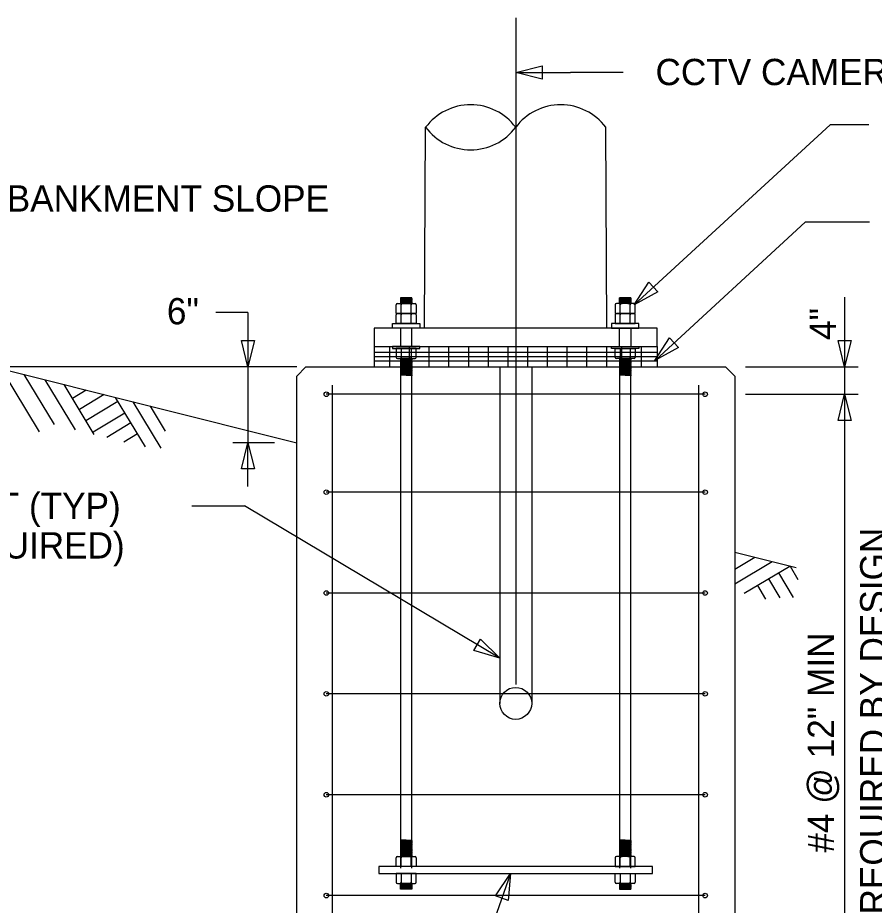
# Model space of a CAD drawing. Extents: x 1299104.6 to 1299141.4, y 239713.3 to 239735.3.
# Drawn here: x 1299109.376 to 1299113.286, y 239719.565 to 239723.616 of the extents above; entities that cross this region are included whole.
import ezdxf

# ---------------------------------------------------------------- set-up
doc = ezdxf.new("R2010")
doc.units = 0
for name, color, linetype in [('DIM TXT', 7, 'Continuous'), ('Level 3', 7, 'Continuous'), ('Level 4', 7, 'Continuous'), ('Level 7', 7, 'Continuous'), ('Level 8', 7, 'Continuous')]:
    doc.layers.add(name, color=color, linetype=linetype)

msp = doc.modelspace()

# ---------------------------------------------------------------- linework, layer by layer
at = {"layer": 'Level 3'}
for p, q in [((1299111.2328, 239722.1991), (1299111.2383, 239723.1157)), ((1299112.0662, 239722.1991), (1299112.0607, 239723.1157)), ((1299108.4734, 239722.22), (1299110.6495, 239721.676)), ((1299112.2953, 239722.1991), (1299111.0037, 239722.1991)), ((1299111.0037, 239722.1991), (1299111.0037, 239722.1157)), ((1299112.2953, 239722.1157), (1299112.2953, 239722.1991)), ((1299111.0037, 239722.1157), (1299112.2953, 239722.1157)), ((1299110.6495, 239721.9803), (1299110.6912, 239722.022)), ((1299110.6912, 239722.022), (1299112.6078, 239722.022)), ((1299111.5766, 239722.022), (1299111.5766, 239720.4861)), ((1299111.7224, 239722.022), (1299111.7224, 239720.4861)), ((1299112.6078, 239722.022), (1299112.6495, 239721.9803)), ((1299110.6495, 239719.022), (1299110.6495, 239721.9803)), ((1299112.6495, 239721.9803), (1299112.6495, 239719.022)), ((1299110.8136, 239718.147), (1299110.8136, 239721.9387)), ((1299112.4854, 239718.147), (1299112.4854, 239721.9387)), ((1299112.5141, 239721.897), (1299110.7849, 239721.897)), ((1299112.5141, 239721.4502), (1299110.7849, 239721.4502)), ((1299112.6495, 239721.176), (1299112.9298, 239721.1059)), ((1299112.5141, 239720.9898), (1299110.7849, 239720.9898)), ((1299112.5141, 239720.5294), (1299110.7849, 239720.5294)), ((1299112.5141, 239720.069), (1299110.7849, 239720.069)), ((1299112.2745, 239719.7411), (1299111.0245, 239719.7411)), ((1299111.0245, 239719.7411), (1299111.0245, 239719.7098)), ((1299112.2745, 239719.7098), (1299112.2745, 239719.7411)), ((1299111.0245, 239719.7098), (1299112.2745, 239719.7098)), ((1299112.5141, 239719.6086), (1299110.7849, 239719.6086))]:
    msp.add_line(p, q, dxfattribs=at)
for centre, radius in [((1299110.7849, 239721.897), 0.0104), ((1299112.5141, 239721.897), 0.0104), ((1299110.7849, 239721.4502), 0.0104), ((1299112.5141, 239721.4502), 0.0104), ((1299110.7849, 239720.9898), 0.0104), ((1299112.5141, 239720.9898), 0.0104), ((1299110.7849, 239720.5294), 0.0104), ((1299111.6495, 239720.4861), 0.0729), ((1299112.5141, 239720.5294), 0.0104), ((1299110.7849, 239720.069), 0.0104), ((1299112.5141, 239720.069), 0.0104), ((1299110.7849, 239719.6086), 0.0104), ((1299112.5141, 239719.6086), 0.0104)]:
    msp.add_circle(centre, radius, dxfattribs=at)
for centre, start, end in [((1299111.4439, 239722.9615), 36.8699, 143.1301), ((1299111.8551, 239722.9615), 36.8699, 143.1301), ((1299111.4439, 239723.2699), 216.8699, 323.1301)]:
    msp.add_arc(centre, 0.257, start, end, dxfattribs=at)
at = {"layer": 'Level 4'}
for p, q in [((1299111.1267, 239722.2655), (1299111.1267, 239722.311)), ((1299111.1723, 239722.2655), (1299111.1723, 239722.311)), ((1299112.1267, 239722.2655), (1299112.1267, 239722.311)), ((1299112.1723, 239722.2655), (1299112.1723, 239722.311)), ((1299111.1267, 239722.2199), (1299111.1267, 239722.2655)), ((1299111.1723, 239722.2199), (1299111.1723, 239722.2655)), ((1299112.1267, 239722.2199), (1299112.1267, 239722.2655)), ((1299112.1723, 239722.2199), (1299112.1723, 239722.2655)), ((1299111.0037, 239722.1157), (1299111.0037, 239722.022)), ((1299111.0732, 239722.1157), (1299111.0732, 239722.022)), ((1299111.1267, 239722.1053), (1299111.1267, 239722.0597)), ((1299111.1632, 239722.1157), (1299111.1632, 239722.022)), ((1299111.1723, 239722.1053), (1299111.1723, 239722.0597)), ((1299111.2532, 239722.1157), (1299111.2532, 239722.022)), ((1299111.3432, 239722.1157), (1299111.3432, 239722.022)), ((1299111.4332, 239722.1157), (1299111.4332, 239722.022)), ((1299111.5232, 239722.1157), (1299111.5232, 239722.022)), ((1299111.6132, 239722.1157), (1299111.6132, 239722.022)), ((1299111.7032, 239722.1157), (1299111.7032, 239722.022)), ((1299111.7932, 239722.1157), (1299111.7932, 239722.022)), ((1299111.8832, 239722.1157), (1299111.8832, 239722.022)), ((1299111.9732, 239722.1157), (1299111.9732, 239722.022)), ((1299112.0632, 239722.1157), (1299112.0632, 239722.022)), ((1299112.1267, 239722.1053), (1299112.1267, 239722.0597)), ((1299112.132, 239722.1157), (1299112.132, 239722.022)), ((1299112.1723, 239722.1053), (1299112.1723, 239722.0597)), ((1299112.222, 239722.1157), (1299112.222, 239722.022)), ((1299112.2953, 239722.1157), (1299112.2953, 239722.022)), ((1299111.0037, 239722.0893), (1299112.2953, 239722.0893)), ((1299111.0037, 239722.0693), (1299112.2953, 239722.0693)), ((1299111.0037, 239722.0493), (1299112.2953, 239722.0493)), ((1299111.1267, 239719.7411), (1299111.1267, 239719.7866)), ((1299111.1723, 239719.7411), (1299111.1723, 239719.7866)), ((1299112.1267, 239719.7411), (1299112.1267, 239719.7866)), ((1299112.1723, 239719.7411), (1299112.1723, 239719.7866)), ((1299111.1267, 239719.7098), (1299111.1267, 239719.6643)), ((1299111.1723, 239719.7098), (1299111.1723, 239719.6643)), ((1299112.1267, 239719.7098), (1299112.1267, 239719.6643)), ((1299112.1723, 239719.7098), (1299112.1723, 239719.6643))]:
    msp.add_line(p, q, dxfattribs=at)
for points in [[(1299111.1093, 239722.311), (1299111.1898, 239722.311)], [(1299111.1755, 239722.311), (1299111.1755, 239722.3371), (1299111.1235, 239722.3371), (1299111.1235, 239722.311)], [(1299111.1755, 239722.3371), (1299111.1235, 239722.3371), (1299111.1755, 239722.3345), (1299111.1755, 239722.3319), (1299111.1235, 239722.3345), (1299111.1235, 239722.3319), (1299111.1755, 239722.3293), (1299111.1755, 239722.3267), (1299111.1235, 239722.3293), (1299111.1235, 239722.3267), (1299111.1755, 239722.3241), (1299111.1755, 239722.3215), (1299111.1235, 239722.3241), (1299111.1235, 239722.3215), (1299111.1755, 239722.3189), (1299111.1755, 239722.3163), (1299111.1235, 239722.3189), (1299111.1235, 239722.3163), (1299111.1755, 239722.3137), (1299111.1755, 239722.311), (1299111.1235, 239722.3137), (1299111.1235, 239722.311)], [(1299112.1898, 239722.311), (1299112.1093, 239722.311)], [(1299112.1235, 239722.311), (1299112.1235, 239722.3371), (1299112.1755, 239722.3371), (1299112.1755, 239722.311)], [(1299112.1755, 239722.3371), (1299112.1235, 239722.3371), (1299112.1755, 239722.3345), (1299112.1755, 239722.3319), (1299112.1235, 239722.3345), (1299112.1235, 239722.3319), (1299112.1755, 239722.3293), (1299112.1755, 239722.3267), (1299112.1235, 239722.3293), (1299112.1235, 239722.3267), (1299112.1755, 239722.3241), (1299112.1755, 239722.3215), (1299112.1235, 239722.3241), (1299112.1235, 239722.3215), (1299112.1755, 239722.3189), (1299112.1755, 239722.3163), (1299112.1235, 239722.3189), (1299112.1235, 239722.3163), (1299112.1755, 239722.3137), (1299112.1755, 239722.311), (1299112.1235, 239722.3137), (1299112.1235, 239722.311)], [(1299111.1951, 239722.3057), (1299111.1951, 239722.2655), (1299111.1039, 239722.2655), (1299111.1039, 239722.3057)], [(1299112.1039, 239722.3057), (1299112.1039, 239722.2655), (1299112.1951, 239722.2655), (1299112.1951, 239722.3057)], [(1299111.1951, 239722.2601), (1299111.1951, 239722.2199), (1299111.1039, 239722.2199), (1299111.1039, 239722.2601)], [(1299111.1093, 239722.2655), (1299111.1898, 239722.2655)], [(1299112.1039, 239722.2601), (1299112.1039, 239722.2199), (1299112.1951, 239722.2199), (1299112.1951, 239722.2601)], [(1299112.1898, 239722.2655), (1299112.1093, 239722.2655)], [(1299111.1755, 239722.1157), (1299111.1755, 239722.1991), (1299111.1235, 239722.1991), (1299111.1235, 239722.1157)], [(1299112.1235, 239722.1157), (1299112.1235, 239722.1991), (1299112.1755, 239722.1991), (1299112.1755, 239722.1157)], [(1299111.1951, 239722.0651), (1299111.1951, 239722.1053), (1299111.1039, 239722.1053), (1299111.1039, 239722.0651)], [(1299112.1039, 239722.0651), (1299112.1039, 239722.1053), (1299112.1951, 239722.1053), (1299112.1951, 239722.0651)], [(1299111.1093, 239722.0597), (1299111.1898, 239722.0597)], [(1299111.1755, 239719.7342), (1299111.1755, 239722.0597), (1299111.1235, 239722.0597), (1299111.1235, 239719.7342)], [(1299111.1755, 239722.0597), (1299111.1235, 239722.0597), (1299111.1755, 239722.0571), (1299111.1755, 239722.0545), (1299111.1235, 239722.0571), (1299111.1235, 239722.0545), (1299111.1755, 239722.0519), (1299111.1755, 239722.0493), (1299111.1235, 239722.0519), (1299111.1235, 239722.0493), (1299111.1755, 239722.0467), (1299111.1755, 239722.0441), (1299111.1235, 239722.0467), (1299111.1235, 239722.0441), (1299111.1755, 239722.0415), (1299111.1755, 239722.0389), (1299111.1235, 239722.0415), (1299111.1235, 239722.0389), (1299111.1755, 239722.0363), (1299111.1755, 239722.0337), (1299111.1235, 239722.0363), (1299111.1235, 239722.0337)], [(1299111.1235, 239722.0337), (1299111.1755, 239722.0311), (1299111.1755, 239722.0285), (1299111.1235, 239722.0311), (1299111.1235, 239722.0285), (1299111.1755, 239722.0259), (1299111.1755, 239722.0233), (1299111.1235, 239722.0259), (1299111.1235, 239722.0233), (1299111.1755, 239722.0207), (1299111.1755, 239722.0181), (1299111.1235, 239722.0207), (1299111.1235, 239722.0181), (1299111.1755, 239722.0155), (1299111.1755, 239722.0129), (1299111.1235, 239722.0155), (1299111.1235, 239722.0129), (1299111.1755, 239722.0103), (1299111.1755, 239722.0077), (1299111.1235, 239722.0103), (1299111.1235, 239722.0077)], [(1299112.1898, 239722.0597), (1299112.1093, 239722.0597)], [(1299112.1755, 239719.7342), (1299112.1755, 239722.0597), (1299112.1235, 239722.0597), (1299112.1235, 239719.7342)], [(1299112.1755, 239722.0597), (1299112.1235, 239722.0597), (1299112.1755, 239722.0571), (1299112.1755, 239722.0545), (1299112.1235, 239722.0571), (1299112.1235, 239722.0545), (1299112.1755, 239722.0519), (1299112.1755, 239722.0493), (1299112.1235, 239722.0519), (1299112.1235, 239722.0493), (1299112.1755, 239722.0467), (1299112.1755, 239722.0441), (1299112.1235, 239722.0467), (1299112.1235, 239722.0441), (1299112.1755, 239722.0415), (1299112.1755, 239722.0389), (1299112.1235, 239722.0415), (1299112.1235, 239722.0389), (1299112.1755, 239722.0363), (1299112.1755, 239722.0337), (1299112.1235, 239722.0363), (1299112.1235, 239722.0337)], [(1299112.1235, 239722.0337), (1299112.1755, 239722.0311), (1299112.1755, 239722.0285), (1299112.1235, 239722.0311), (1299112.1235, 239722.0285), (1299112.1755, 239722.0259), (1299112.1755, 239722.0233), (1299112.1235, 239722.0259), (1299112.1235, 239722.0233), (1299112.1755, 239722.0207), (1299112.1755, 239722.0181), (1299112.1235, 239722.0207), (1299112.1235, 239722.0181), (1299112.1755, 239722.0155), (1299112.1755, 239722.0129), (1299112.1235, 239722.0155), (1299112.1235, 239722.0129), (1299112.1755, 239722.0103), (1299112.1755, 239722.0077), (1299112.1235, 239722.0103), (1299112.1235, 239722.0077)], [(1299111.1235, 239722.0077), (1299111.1755, 239722.0051), (1299111.1755, 239722.0025), (1299111.1235, 239722.0051), (1299111.1235, 239722.0025), (1299111.1755, 239721.9998), (1299111.1755, 239721.9972), (1299111.1235, 239721.9998), (1299111.1235, 239721.9972), (1299111.1755, 239721.9946), (1299111.1755, 239721.992), (1299111.1235, 239721.9946), (1299111.1235, 239721.992), (1299111.1755, 239721.9894), (1299111.1755, 239721.9868), (1299111.1235, 239721.9894), (1299111.1235, 239721.9868), (1299111.1755, 239721.9842), (1299111.1755, 239721.9816), (1299111.1235, 239721.9842), (1299111.1235, 239721.9816)], [(1299112.1235, 239722.0077), (1299112.1755, 239722.0051), (1299112.1755, 239722.0025), (1299112.1235, 239722.0051), (1299112.1235, 239722.0025), (1299112.1755, 239721.9998), (1299112.1755, 239721.9972), (1299112.1235, 239721.9998), (1299112.1235, 239721.9972), (1299112.1755, 239721.9946), (1299112.1755, 239721.992), (1299112.1235, 239721.9946), (1299112.1235, 239721.992), (1299112.1755, 239721.9894), (1299112.1755, 239721.9868), (1299112.1235, 239721.9894), (1299112.1235, 239721.9868), (1299112.1755, 239721.9842), (1299112.1755, 239721.9816), (1299112.1235, 239721.9842), (1299112.1235, 239721.9816)], [(1299111.1235, 239719.8648), (1299111.1755, 239719.8622), (1299111.1755, 239719.8596), (1299111.1235, 239719.8622), (1299111.1235, 239719.8596), (1299111.1755, 239719.857), (1299111.1755, 239719.8544), (1299111.1235, 239719.857), (1299111.1235, 239719.8544), (1299111.1755, 239719.8518), (1299111.1755, 239719.8491), (1299111.1235, 239719.8518), (1299111.1235, 239719.8491), (1299111.1755, 239719.8465), (1299111.1755, 239719.8439), (1299111.1235, 239719.8465), (1299111.1235, 239719.8439), (1299111.1755, 239719.8413), (1299111.1755, 239719.8387), (1299111.1235, 239719.8413), (1299111.1235, 239719.8387)], [(1299111.1235, 239719.8387), (1299111.1755, 239719.8361), (1299111.1755, 239719.8335), (1299111.1235, 239719.8361), (1299111.1235, 239719.8335), (1299111.1755, 239719.8309), (1299111.1755, 239719.8283), (1299111.1235, 239719.8309), (1299111.1235, 239719.8283), (1299111.1755, 239719.8257), (1299111.1755, 239719.8231), (1299111.1235, 239719.8257), (1299111.1235, 239719.8231), (1299111.1755, 239719.8205), (1299111.1755, 239719.8179), (1299111.1235, 239719.8205), (1299111.1235, 239719.8179), (1299111.1755, 239719.8153), (1299111.1755, 239719.8127), (1299111.1235, 239719.8153), (1299111.1235, 239719.8127)], [(1299112.1235, 239719.8648), (1299112.1755, 239719.8622), (1299112.1755, 239719.8596), (1299112.1235, 239719.8622), (1299112.1235, 239719.8596), (1299112.1755, 239719.857), (1299112.1755, 239719.8544), (1299112.1235, 239719.857), (1299112.1235, 239719.8544), (1299112.1755, 239719.8518), (1299112.1755, 239719.8491), (1299112.1235, 239719.8518), (1299112.1235, 239719.8491), (1299112.1755, 239719.8465), (1299112.1755, 239719.8439), (1299112.1235, 239719.8465), (1299112.1235, 239719.8439), (1299112.1755, 239719.8413), (1299112.1755, 239719.8387), (1299112.1235, 239719.8413), (1299112.1235, 239719.8387)], [(1299112.1235, 239719.8387), (1299112.1755, 239719.8361), (1299112.1755, 239719.8335), (1299112.1235, 239719.8361), (1299112.1235, 239719.8335), (1299112.1755, 239719.8309), (1299112.1755, 239719.8283), (1299112.1235, 239719.8309), (1299112.1235, 239719.8283), (1299112.1755, 239719.8257), (1299112.1755, 239719.8231), (1299112.1235, 239719.8257), (1299112.1235, 239719.8231), (1299112.1755, 239719.8205), (1299112.1755, 239719.8179), (1299112.1235, 239719.8205), (1299112.1235, 239719.8179), (1299112.1755, 239719.8153), (1299112.1755, 239719.8127), (1299112.1235, 239719.8153), (1299112.1235, 239719.8127)], [(1299111.1235, 239719.8127), (1299111.1755, 239719.8101), (1299111.1755, 239719.8075), (1299111.1235, 239719.8101), (1299111.1235, 239719.8075), (1299111.1755, 239719.8049), (1299111.1755, 239719.8023), (1299111.1235, 239719.8049), (1299111.1235, 239719.8023), (1299111.1755, 239719.7997), (1299111.1755, 239719.7971), (1299111.1235, 239719.7997), (1299111.1235, 239719.7971), (1299111.1755, 239719.7945), (1299111.1755, 239719.7919), (1299111.1235, 239719.7945), (1299111.1235, 239719.7919), (1299111.1755, 239719.7893), (1299111.1755, 239719.7866), (1299111.1235, 239719.7893), (1299111.1235, 239719.7866)], [(1299112.1235, 239719.8127), (1299112.1755, 239719.8101), (1299112.1755, 239719.8075), (1299112.1235, 239719.8101), (1299112.1235, 239719.8075), (1299112.1755, 239719.8049), (1299112.1755, 239719.8023), (1299112.1235, 239719.8049), (1299112.1235, 239719.8023), (1299112.1755, 239719.7997), (1299112.1755, 239719.7971), (1299112.1235, 239719.7997), (1299112.1235, 239719.7971), (1299112.1755, 239719.7945), (1299112.1755, 239719.7919), (1299112.1235, 239719.7945), (1299112.1235, 239719.7919), (1299112.1755, 239719.7893), (1299112.1755, 239719.7866), (1299112.1235, 239719.7893), (1299112.1235, 239719.7866)], [(1299111.1951, 239719.7813), (1299111.1951, 239719.7411), (1299111.1039, 239719.7411), (1299111.1039, 239719.7813)], [(1299111.1093, 239719.7866), (1299111.1898, 239719.7866)], [(1299112.1039, 239719.7813), (1299112.1039, 239719.7411), (1299112.1951, 239719.7411), (1299112.1951, 239719.7813)], [(1299112.1898, 239719.7866), (1299112.1093, 239719.7866)], [(1299111.1951, 239719.6696), (1299111.1951, 239719.7098), (1299111.1039, 239719.7098), (1299111.1039, 239719.6696)], [(1299112.1039, 239719.6696), (1299112.1039, 239719.7098), (1299112.1951, 239719.7098), (1299112.1951, 239719.6696)], [(1299111.1093, 239719.6643), (1299111.1898, 239719.6643)], [(1299111.1755, 239719.6643), (1299111.1755, 239719.6382), (1299111.1235, 239719.6382), (1299111.1235, 239719.6643)], [(1299111.1755, 239719.6643), (1299111.1235, 239719.6643), (1299111.1755, 239719.6616), (1299111.1755, 239719.659), (1299111.1235, 239719.6616), (1299111.1235, 239719.659), (1299111.1755, 239719.6564), (1299111.1755, 239719.6538), (1299111.1235, 239719.6564), (1299111.1235, 239719.6538), (1299111.1755, 239719.6512), (1299111.1755, 239719.6486), (1299111.1235, 239719.6512), (1299111.1235, 239719.6486), (1299111.1755, 239719.646), (1299111.1755, 239719.6434), (1299111.1235, 239719.646), (1299111.1235, 239719.6434), (1299111.1755, 239719.6408), (1299111.1755, 239719.6382), (1299111.1235, 239719.6408), (1299111.1235, 239719.6382)], [(1299112.1898, 239719.6643), (1299112.1093, 239719.6643)], [(1299112.1235, 239719.6643), (1299112.1235, 239719.6382), (1299112.1755, 239719.6382), (1299112.1755, 239719.6643)], [(1299112.1755, 239719.6643), (1299112.1235, 239719.6643), (1299112.1755, 239719.6616), (1299112.1755, 239719.659), (1299112.1235, 239719.6616), (1299112.1235, 239719.659), (1299112.1755, 239719.6564), (1299112.1755, 239719.6538), (1299112.1235, 239719.6564), (1299112.1235, 239719.6538), (1299112.1755, 239719.6512), (1299112.1755, 239719.6486), (1299112.1235, 239719.6512), (1299112.1235, 239719.6486), (1299112.1755, 239719.646), (1299112.1755, 239719.6434), (1299112.1235, 239719.646), (1299112.1235, 239719.6434), (1299112.1755, 239719.6408), (1299112.1755, 239719.6382), (1299112.1235, 239719.6408), (1299112.1235, 239719.6382)]]:
    msp.add_lwpolyline(points, dxfattribs=at)
for points in [[(1299111.212, 239722.1991), (1299111.087, 239722.1991), (1299111.087, 239722.2199), (1299111.212, 239722.2199)], [(1299112.087, 239722.1991), (1299112.212, 239722.1991), (1299112.212, 239722.2199), (1299112.087, 239722.2199)], [(1299111.212, 239722.1157), (1299111.087, 239722.1157), (1299111.087, 239722.1053), (1299111.212, 239722.1053)], [(1299112.087, 239722.1157), (1299112.212, 239722.1157), (1299112.212, 239722.1053), (1299112.087, 239722.1053)]]:
    msp.add_lwpolyline(points, close=True, dxfattribs=at)
for centre, start, end in [((1299111.1093, 239722.3057), 90, 180), ((1299111.1214, 239722.3057), 0, 90), ((1299111.1776, 239722.3057), 90, 180), ((1299111.1898, 239722.3057), 0, 90), ((1299112.1093, 239722.3057), 90, 180), ((1299112.1214, 239722.3057), 0, 90), ((1299112.1776, 239722.3057), 90, 180), ((1299112.1898, 239722.3057), 0, 90), ((1299111.1093, 239722.2601), 90, 180), ((1299111.1214, 239722.2601), 0, 90), ((1299111.1776, 239722.2601), 90, 180), ((1299111.1898, 239722.2601), 0, 90), ((1299112.1093, 239722.2601), 90, 180), ((1299112.1214, 239722.2601), 0, 90), ((1299112.1776, 239722.2601), 90, 180), ((1299112.1898, 239722.2601), 0, 90), ((1299111.1093, 239722.0651), 180, 270), ((1299111.1214, 239722.0651), 270, 360), ((1299111.1776, 239722.0651), 180, 270), ((1299111.1898, 239722.0651), 270, 360), ((1299112.1093, 239722.0651), 180, 270), ((1299112.1214, 239722.0651), 270, 360), ((1299112.1776, 239722.0651), 180, 270), ((1299112.1898, 239722.0651), 270, 360), ((1299111.1093, 239719.7813), 90, 180), ((1299111.1214, 239719.7813), 0, 90), ((1299111.1776, 239719.7813), 90, 180), ((1299111.1898, 239719.7813), 0, 90), ((1299112.1093, 239719.7813), 90, 180), ((1299112.1214, 239719.7813), 0, 90), ((1299112.1776, 239719.7813), 90, 180), ((1299112.1898, 239719.7813), 0, 90), ((1299111.1093, 239719.6696), 180, 270), ((1299111.1214, 239719.6696), 270, 360), ((1299111.1776, 239719.6696), 180, 270), ((1299111.1898, 239719.6696), 270, 360), ((1299112.1093, 239719.6696), 180, 270), ((1299112.1214, 239719.6696), 270, 360), ((1299112.1776, 239719.6696), 180, 270), ((1299112.1898, 239719.6696), 270, 360)]:
    msp.add_arc(centre, 0.00533, start, end, dxfattribs=at)
for centre, major_axis, start_param, end_param in [((1299111.1414, 239722.3057), (-0.0147, 0), 4.712389, 6.283185), ((1299111.1576, 239722.3057), (0.0147, 0), 0, 1.570796), ((1299112.1414, 239722.3057), (-0.0147, 0), 4.712389, 6.283185), ((1299112.1576, 239722.3057), (0.0147, 0), 0, 1.570796), ((1299111.1414, 239722.2601), (-0.0147, 0), 4.712389, 6.283185), ((1299111.1576, 239722.2601), (0.0147, 0), 0, 1.570796), ((1299112.1414, 239722.2601), (-0.0147, 0), 4.712389, 6.283185), ((1299112.1576, 239722.2601), (0.0147, 0), 0, 1.570796), ((1299111.1414, 239722.0651), (-0.0147, 0), 0, 1.570796), ((1299111.1576, 239722.0651), (0.0147, 0), 4.712389, 6.283185), ((1299112.1414, 239722.0651), (-0.0147, 0), 0, 1.570796), ((1299112.1576, 239722.0651), (0.0147, 0), 4.712389, 6.283185), ((1299111.1414, 239719.7813), (-0.0147, 0), 4.712389, 6.283185), ((1299111.1576, 239719.7813), (0.0147, 0), 0, 1.570796), ((1299112.1414, 239719.7813), (-0.0147, 0), 4.712389, 6.283185), ((1299112.1576, 239719.7813), (0.0147, 0), 0, 1.570796), ((1299111.1414, 239719.6696), (-0.0147, 0), 0, 1.570796), ((1299111.1576, 239719.6696), (0.0147, 0), 4.712389, 6.283185), ((1299112.1414, 239719.6696), (-0.0147, 0), 0, 1.570796), ((1299112.1576, 239719.6696), (0.0147, 0), 4.712389, 6.283185)]:
    msp.add_ellipse(centre, major_axis=major_axis, ratio=0.362172, start_param=start_param, end_param=end_param, dxfattribs=at)
at = {"layer": 'Level 7'}
msp.add_line((1299111.6495, 239723.6157), (1299111.6495, 239720.5725), dxfattribs=at)
at = {"layer": 'Level 8'}
for p, q in [((1299111.6495, 239723.3657), (1299111.8995, 239723.3657)), ((1299112.1395, 239723.3657), (1299111.8995, 239723.3657)), ((1299112.1898, 239722.3057), (1299113.0845, 239723.1276)), ((1299113.262, 239723.1276), (1299113.0845, 239723.1276)), ((1299112.288, 239722.0529), (1299112.9714, 239722.6829)), ((1299113.2641, 239722.6829), (1299112.9714, 239722.6829)), ((1299113.151, 239722.3405), (1299113.151, 239718.61)), ((1299110.4269, 239722.2699), (1299110.2809, 239722.2699)), ((1299110.4269, 239722.2699), (1299110.4269, 239722.022)), ((1299110.6071, 239722.022), (1299108.3022, 239722.022)), ((1299109.4754, 239721.7261), (1299109.3019, 239722.0129)), ((1299109.5432, 239721.759), (1299109.4052, 239721.9871)), ((1299110.6503, 239722.022), (1299109.9589, 239722.022)), ((1299110.4269, 239722.022), (1299110.4269, 239721.676)), ((1299112.698, 239722.022), (1299113.2125, 239722.022)), ((1299109.6397, 239721.7349), (1299109.5016, 239721.963)), ((1299109.7253, 239721.7138), (1299109.5875, 239721.9415)), ((1299109.6892, 239721.9161), (1299109.6261, 239721.8779)), ((1299109.7709, 239721.8957), (1299109.6576, 239721.8271)), ((1299109.833, 239721.8642), (1299109.687, 239721.7759)), ((1299109.9587, 239721.6565), (1299109.8217, 239721.883)), ((1299110.0309, 239721.6512), (1299109.903, 239721.8626)), ((1299112.698, 239721.897), (1299113.2125, 239721.897)), ((1299110.0505, 239721.7291), (1299109.9816, 239721.843)), ((1299109.8649, 239721.8115), (1299109.72, 239721.7238)), ((1299109.8922, 239721.7665), (1299109.7821, 239721.6999)), ((1299109.9226, 239721.716), (1299109.8598, 239721.6779)), ((1299110.5478, 239721.676), (1299110.3581, 239721.676)), ((1299110.4269, 239721.4765), (1299110.4269, 239721.676)), ((1299110.1708, 239721.3873), (1299110.4108, 239721.3873)), ((1299111.5766, 239720.692), (1299110.4108, 239721.3873)), ((1299112.6494, 239721.0983), (1299112.741, 239721.1528)), ((1299112.6494, 239721.0319), (1299112.8197, 239721.1332)), ((1299112.6929, 239720.989), (1299112.901, 239721.1129)), ((1299112.9019, 239721.1126), (1299112.9379, 239721.0522)), ((1299112.8034, 239721.0548), (1299112.8551, 239720.9678)), ((1299112.8486, 239721.0817), (1299112.9154, 239720.9693)), ((1299112.7527, 239721.0246), (1299112.7902, 239720.9614)), ((1299111.6264, 239719.7098), (1299110.8628, 239717.5674))]:
    msp.add_line(p, q, dxfattribs=at)
for points in [[(1299111.7695, 239723.3357), (1299111.6495, 239723.3657), (1299111.7695, 239723.3957)], [(1299112.2984, 239722.3648), (1299112.1898, 239722.3057), (1299112.2578, 239722.409)], [(1299112.3928, 239722.1108), (1299112.2845, 239722.0509), (1299112.3519, 239722.1547)], [(1299110.4569, 239722.142), (1299110.4269, 239722.022), (1299110.3969, 239722.142)], [(1299113.181, 239722.142), (1299113.151, 239722.022), (1299113.121, 239722.142)], [(1299113.121, 239721.777), (1299113.151, 239721.897), (1299113.181, 239721.777)], [(1299110.3969, 239721.556), (1299110.4269, 239721.676), (1299110.4569, 239721.556)], [(1299111.4889, 239720.7792), (1299111.5766, 239720.692), (1299111.4582, 239720.7277)], [(1299111.5578, 239719.6069), (1299111.6264, 239719.7098), (1299111.6143, 239719.5867)]]:
    msp.add_lwpolyline(points, close=True, dxfattribs=at)

# ---------------------------------------------------------------- texts
at = {"layer": 'DIM TXT'}
for s, p in [('  CCTV CAMERA POLE', (1299112.1986, 239723.3081)), ('EMBANKMENT SLOPE', (1299109.0853, 239722.7309)), ('CONDUIT (TYP)', (1299108.6519, 239721.3273)), ('(AS REQUIRED)', (1299108.6519, 239721.1473))]:
    msp.add_text(s, height=0.12, dxfattribs=at).set_placement(p)
for s, rotation, p in [('6"', 360, (1299110.057, 239722.2163)), ('4"', 90, (1299113.1112, 239722.1448)), ('AS REQUIRED BY DESIGN', 90, (1299113.3418, 239719.2638)), ('#4 @ 12" MIN', 90, (1299113.103, 239719.8047))]:
    msp.add_text(s, height=0.12, rotation=rotation, dxfattribs=at).set_placement(p)

doc.saveas('drawing.dxf')
